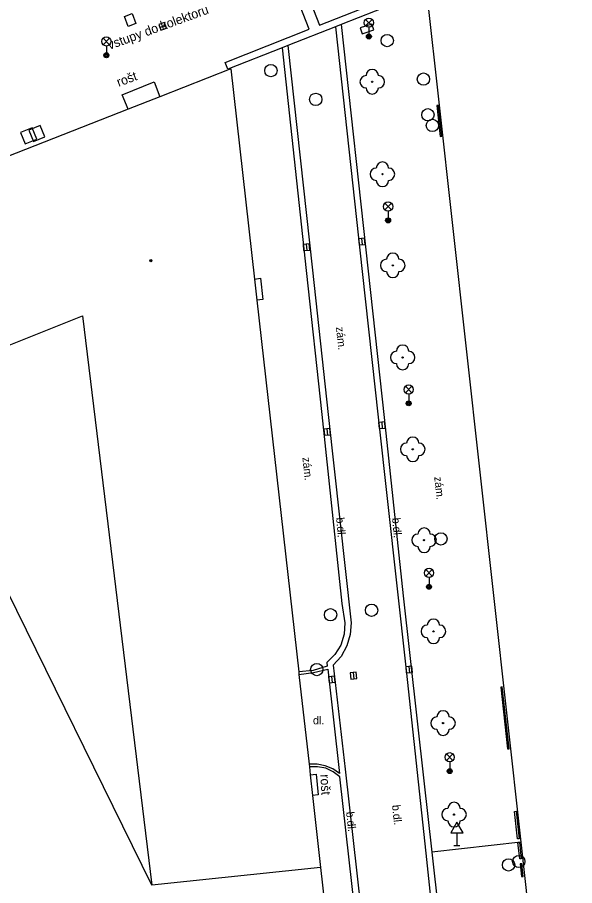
# Model space of a CAD drawing. Extents: x -598341 to -594502, y -1162301 to -1161406.
# Drawn here: x -597857.8 to -597812.6, y -1161565 to -1161494.5 of the extents above; entities that cross this region are included whole.
import ezdxf

# ---------------------------------------------------------------- set-up
doc = ezdxf.new("R2010")
doc.units = 0
for name, color, linetype in [('Vrstva 10', 7, 'Continuous'), ('Vrstva 11', 7, 'Continuous'), ('Vrstva 22', 7, 'Continuous'), ('Vrstva 24', 7, 'Continuous'), ('Vrstva 26', 7, 'Continuous'), ('Vrstva 27', 7, 'Continuous'), ('Vrstva 33', 7, 'Continuous'), ('Vrstva 34', 7, 'Continuous'), ('Vrstva 39', 7, 'Continuous'), ('Vrstva 40', 7, 'Continuous'), ('Vrstva 42', 7, 'Continuous'), ('Vrstva 5', 7, 'Continuous')]:
    doc.layers.add(name, color=color, linetype=linetype)

msp = doc.modelspace()

# ---------------------------------------------------------------- linework, layer by layer
at = {"layer": 'Vrstva 10'}
for points in [[(-597832.03, -1161495.26), (-597835.89, -1161496.78)], [(-597832.03, -1161495.26), (-597829.87, -1161515.13), (-597828.57, -1161526.96), (-597826.29, -1161547.51), (-597824.69, -1161562.35), (-597823.68, -1161571.89), (-597822.03, -1161587.03), (-597820.44, -1161601.59), (-597818.83, -1161616.03), (-597818.07, -1161622.89)], [(-597835.89, -1161496.78), (-597833.9, -1161515.03), (-597832.61, -1161526.75), (-597830.76, -1161543.65), (-597830.82, -1161544.61), (-597831.09, -1161545.53), (-597831.56, -1161546.38), (-597832.2, -1161547.09)], [(-597832.2, -1161547.09), (-597831.25, -1161555.55), (-597828.73, -1161577.99), (-597827.17, -1161591.96), (-597827.31, -1161592.41), (-597827.31, -1161592.92), (-597827.19, -1161593.38), (-597826.94, -1161593.81), (-597825.4, -1161607.71), (-597823.85, -1161621.6), (-597824.07, -1161623.12), (-597824.6, -1161624.55), (-597825.33, -1161625.58), (-597826.2, -1161626.54)]]:
    msp.add_lwpolyline(points, dxfattribs=at)
at = {"layer": 'Vrstva 11'}
for points in [[(-597836.36, -1161496.96), (-597840.77, -1161498.7), (-597840.99, -1161498.15), (-597834.16, -1161495.44), (-597838.87, -1161483.39), (-597838.03, -1161483.06)], [(-597838.03, -1161483.06), (-597833.31, -1161495.12), (-597824.54, -1161491.66), (-597824.34, -1161492.23)], [(-597824.65, -1161492.35), (-597831.55, -1161495.07)], [(-597849.16, -1161494.43), (-597848.54, -1161494.19), (-597848.23, -1161494.99), (-597848.85, -1161495.23), (-597849.16, -1161494.43)], [(-597831.55, -1161495.07), (-597832.03, -1161495.26)], [(-597831.55, -1161495.07), (-597829.38, -1161515.1), (-597828.08, -1161526.98), (-597826.53, -1161541.46), (-597824.84, -1161556.49), (-597824.2, -1161562.28)], [(-597835.89, -1161496.78), (-597836.36, -1161496.96)], [(-597836.36, -1161496.96), (-597834.39, -1161515.05), (-597833.12, -1161526.73), (-597831.5, -1161542.08), (-597831.27, -1161543.67), (-597831.32, -1161544.58), (-597831.59, -1161545.46), (-597832.07, -1161546.24), (-597832.73, -1161546.87), (-597832.7, -1161547.19), (-597833.83, -1161547.53), (-597835.01, -1161547.65)], [(-597848.84, -1161501.95), (-597849.35, -1161500.77), (-597846.75, -1161499.74), (-597846.27, -1161500.94)], [(-597823.67, -1161501.64), (-597823.8, -1161501.65), (-597823.52, -1161504.16), (-597823.39, -1161504.15), (-597823.67, -1161501.64)], [(-597838.59, -1161515.75), (-597838.12, -1161515.68), (-597837.91, -1161517.39), (-597838.4, -1161517.45)], [(-597834.99, -1161547.85), (-597833.8, -1161547.7), (-597832.65, -1161547.41), (-597831.71, -1161555.9), (-597832.25, -1161555.52), (-597832.86, -1161555.26), (-597833.51, -1161555.13), (-597834.17, -1161555.14)], [(-597818.48, -1161548.86), (-597818.61, -1161548.87), (-597818.06, -1161553.89), (-597817.93, -1161553.88), (-597818.48, -1161548.86)], [(-597824.88, -1161624.03), (-597824.49, -1161622.94), (-597824.31, -1161621.67), (-597825.86, -1161607.9), (-597827.41, -1161594.12), (-597827.66, -1161593.64), (-597827.78, -1161593.11), (-597827.78, -1161592.54), (-597827.66, -1161592.04), (-597829.22, -1161578.05), (-597831.67, -1161556.17), (-597832.2, -1161555.75), (-597832.81, -1161555.47), (-597833.47, -1161555.34), (-597834.14, -1161555.36)], [(-597834.07, -1161556), (-597833.6, -1161555.94), (-597833.43, -1161557.64), (-597833.88, -1161557.68)], [(-597817.49, -1161558.97), (-597817.36, -1161558.96), (-597817.11, -1161561.19), (-597817.24, -1161561.2), (-597817.49, -1161558.97)], [(-597816.98, -1161561.47), (-597824.2, -1161562.28)], [(-597817.09, -1161561.49), (-597816.94, -1161562.82), (-597817.07, -1161562.83), (-597817.22, -1161561.5), (-597817.09, -1161561.49)], [(-597824.2, -1161562.28), (-597823.13, -1161571.98), (-597821.53, -1161586.98), (-597819.94, -1161601.53), (-597819.94, -1161601.55)], [(-597816.92, -1161564.26), (-597816.79, -1161564.25), (-597816.9, -1161563.22), (-597817.03, -1161563.23), (-597816.92, -1161564.26)]]:
    msp.add_lwpolyline(points, dxfattribs=at)
at = {"layer": 'Vrstva 22'}
for centre in [(-597829.04, -1161499.72), (-597828.21, -1161507.23), (-597827.37, -1161514.63), (-597826.57, -1161522.11), (-597825.75, -1161529.57), (-597824.83, -1161536.95), (-597824.07, -1161544.35), (-597823.29, -1161551.8), (-597822.4, -1161559.23)]:
    msp.add_circle(centre, 0.05, dxfattribs=at)
for centre, start, end in [((-597829.04, -1161499.22), 0, 180), ((-597829.54, -1161499.72), 90, 270), ((-597828.54, -1161499.72), 270, 90), ((-597829.04, -1161500.22), 180, 0), ((-597828.21, -1161506.73), 0, 180), ((-597828.71, -1161507.23), 90, 270), ((-597827.71, -1161507.23), 270, 90), ((-597828.21, -1161507.73), 180, 0), ((-597827.37, -1161514.13), 0, 180), ((-597827.87, -1161514.63), 90, 270), ((-597826.87, -1161514.63), 270, 90), ((-597827.37, -1161515.13), 180, 0), ((-597826.57, -1161521.61), 0, 180), ((-597827.07, -1161522.11), 90, 270), ((-597826.07, -1161522.11), 270, 90), ((-597826.57, -1161522.61), 180, 0), ((-597826.25, -1161529.57), 90, 270), ((-597825.75, -1161529.07), 0, 180), ((-597825.25, -1161529.57), 270, 90), ((-597825.75, -1161530.07), 180, 0), ((-597824.83, -1161536.45), 0, 180), ((-597825.33, -1161536.95), 90, 270), ((-597824.33, -1161536.95), 270, 90), ((-597824.83, -1161537.45), 180, 0), ((-597824.07, -1161543.85), 0, 180), ((-597824.57, -1161544.35), 90, 270), ((-597823.57, -1161544.35), 270, 90), ((-597824.07, -1161544.85), 180, 0), ((-597823.29, -1161551.3), 0, 180), ((-597823.79, -1161551.8), 90, 270), ((-597822.79, -1161551.8), 270, 90), ((-597823.29, -1161552.3), 180, 0), ((-597822.9, -1161559.23), 90, 270), ((-597822.4, -1161558.73), 0, 180), ((-597821.9, -1161559.23), 270, 90), ((-597822.4, -1161559.73), 180, 0)]:
    msp.add_arc(centre, 0.5, start, end, dxfattribs=at)
at = {"layer": 'Vrstva 24'}
msp.add_lwpolyline([(-597829.867, -1161495.824), (-597828.917, -1161495.511), (-597829.073, -1161495.036), (-597830.023, -1161495.349)], close=True, dxfattribs=at)
at = {"layer": 'Vrstva 26'}
for points in [[(-597857.206, -1161504.771), (-597856.279, -1161504.396), (-597856.654, -1161503.469), (-597857.581, -1161503.844)], [(-597856.536, -1161504.581), (-597855.609, -1161504.206), (-597855.984, -1161503.279), (-597856.911, -1161503.654)]]:
    msp.add_lwpolyline(points, close=True, dxfattribs=at)
at = {"layer": 'Vrstva 27'}
for p, q in [((-597846.285, -1161495.306), (-597845.815, -1161495.134)), ((-597834.403, -1161512.911), (-597834.357, -1161513.409)), ((-597829.903, -1161512.451), (-597829.857, -1161512.949)), ((-597828.273, -1161527.371), (-597828.227, -1161527.869)), ((-597832.723, -1161527.911), (-597832.677, -1161528.409)), ((-597826.073, -1161547.211), (-597826.027, -1161547.709)), ((-597832.343, -1161548.011), (-597832.297, -1161548.509)), ((-597830.583, -1161547.701), (-597830.537, -1161548.199))]:
    msp.add_line(p, q, dxfattribs=at)
for points in [[(-597846.2, -1161495.54), (-597845.729, -1161495.369), (-597845.9, -1161494.9), (-597846.371, -1161495.071)], [(-597834.652, -1161512.934), (-597834.606, -1161513.432), (-597834.108, -1161513.386), (-597834.154, -1161512.888)], [(-597830.152, -1161512.474), (-597830.106, -1161512.972), (-597829.608, -1161512.926), (-597829.654, -1161512.428)], [(-597828.522, -1161527.394), (-597828.476, -1161527.892), (-597827.978, -1161527.846), (-597828.024, -1161527.348)], [(-597832.972, -1161527.934), (-597832.926, -1161528.432), (-597832.428, -1161528.386), (-597832.474, -1161527.888)], [(-597826.322, -1161547.234), (-597826.276, -1161547.732), (-597825.778, -1161547.686), (-597825.824, -1161547.188)], [(-597832.592, -1161548.034), (-597832.546, -1161548.532), (-597832.048, -1161548.486), (-597832.094, -1161547.988)], [(-597830.832, -1161547.724), (-597830.786, -1161548.222), (-597830.288, -1161548.176), (-597830.334, -1161547.678)]]:
    msp.add_lwpolyline(points, close=True, dxfattribs=at)
for centre in [(-597827.82, -1161496.38), (-597837.27, -1161498.82), (-597824.88, -1161499.51), (-597833.63, -1161501.15), (-597824.52, -1161502.4), (-597824.16, -1161503.27), (-597823.46, -1161536.84), (-597832.42, -1161543), (-597829.09, -1161542.64), (-597833.54, -1161547.45), (-597817.97, -1161563.32), (-597817.14, -1161563.04)]:
    msp.add_circle(centre, 0.5, dxfattribs=at)
at = {"layer": 'Vrstva 33'}
for p, q in [((-597829.575, -1161495.19), (-597829.045, -1161494.66)), ((-597829.575, -1161494.66), (-597829.045, -1161495.19)), ((-597829.31, -1161495.3), (-597829.31, -1161496.05)), ((-597850.885, -1161496.71), (-597850.355, -1161496.18)), ((-597850.885, -1161496.18), (-597850.355, -1161496.71)), ((-597850.62, -1161496.82), (-597850.62, -1161497.57)), ((-597828.015, -1161510.12), (-597827.485, -1161509.59)), ((-597828.015, -1161509.59), (-597827.485, -1161510.12)), ((-597827.75, -1161510.23), (-597827.75, -1161510.98)), ((-597826.345, -1161524.98), (-597825.815, -1161524.45)), ((-597826.345, -1161524.45), (-597825.815, -1161524.98)), ((-597826.08, -1161525.09), (-597826.08, -1161525.84)), ((-597824.695, -1161539.87), (-597824.165, -1161539.34)), ((-597824.695, -1161539.34), (-597824.165, -1161539.87)), ((-597824.43, -1161539.98), (-597824.43, -1161540.73)), ((-597823.015, -1161554.84), (-597822.485, -1161554.31)), ((-597823.015, -1161554.31), (-597822.485, -1161554.84)), ((-597822.75, -1161554.95), (-597822.75, -1161555.7))]:
    msp.add_line(p, q, dxfattribs=at)
for centre, radius in [((-597829.31, -1161494.925), 0.375), ((-597850.62, -1161496.445), 0.375), ((-597829.31, -1161496.05), 0.2), ((-597829.31, -1161496.05), 0.145), ((-597829.31, -1161496.05), 0.0876), ((-597850.62, -1161497.57), 0.2), ((-597850.62, -1161497.57), 0.145), ((-597850.62, -1161497.57), 0.0876), ((-597827.75, -1161509.855), 0.375), ((-597827.75, -1161510.98), 0.2), ((-597827.75, -1161510.98), 0.145), ((-597827.75, -1161510.98), 0.0876), ((-597826.08, -1161524.715), 0.375), ((-597826.08, -1161525.84), 0.2), ((-597826.08, -1161525.84), 0.145), ((-597826.08, -1161525.84), 0.0876), ((-597824.43, -1161539.605), 0.375), ((-597824.43, -1161540.73), 0.2), ((-597824.43, -1161540.73), 0.145), ((-597824.43, -1161540.73), 0.0876), ((-597822.75, -1161554.575), 0.375), ((-597822.75, -1161555.7), 0.2), ((-597822.75, -1161555.7), 0.145), ((-597822.75, -1161555.7), 0.0876)]:
    msp.add_circle(centre, radius, dxfattribs=at)
at = {"layer": 'Vrstva 34'}
for p, q in [((-597822.17, -1161560.722), (-597822.17, -1161561.74)), ((-597822.42, -1161561.74), (-597821.92, -1161561.74))]:
    msp.add_line(p, q, dxfattribs=at)
msp.add_lwpolyline([(-597822.67, -1161560.722), (-597821.67, -1161560.722), (-597822.17, -1161559.856)], close=True, dxfattribs=at)
at = {"layer": 'Vrstva 39'}
for radius in [0.09, 0.0398]:
    msp.add_circle((-597847.01, -1161514.25), radius, dxfattribs=at)
at = {"layer": 'Vrstva 5'}
for p, q in [((-597824.65, -1161492.35), (-597823.62, -1161501.38)), ((-597840.51, -1161498.68), (-597846.27, -1161500.94)), ((-597840.51, -1161498.68), (-597838.59, -1161515.75)), ((-597846.27, -1161500.94), (-597848.84, -1161501.95)), ((-597823.62, -1161501.38), (-597816.98, -1161561.47)), ((-597848.84, -1161501.95), (-597872, -1161511.03)), ((-597838.59, -1161515.75), (-597838.4, -1161517.45)), ((-597838.4, -1161517.45), (-597835.01, -1161547.65)), ((-597866.58, -1161524.34), (-597852.57, -1161518.72)), ((-597852.57, -1161518.72), (-597846.94, -1161564.96)), ((-597846.94, -1161564.96), (-597865, -1161528.22)), ((-597835.01, -1161547.65), (-597834.99, -1161547.85)), ((-597834.99, -1161547.85), (-597834.17, -1161555.14)), ((-597834.17, -1161555.14), (-597834.14, -1161555.36)), ((-597834.14, -1161555.36), (-597834.07, -1161556)), ((-597834.07, -1161556), (-597833.88, -1161557.68)), ((-597833.88, -1161557.68), (-597833.23, -1161563.52)), ((-597816.98, -1161561.47), (-597812.61, -1161600.77)), ((-597833.23, -1161563.52), (-597846.94, -1161564.96)), ((-597833.23, -1161563.52), (-597831.06, -1161582.82))]:
    msp.add_line(p, q, dxfattribs=at)

# ---------------------------------------------------------------- texts
at = {"layer": 'Vrstva 40'}
for s, rotation, p in [('zám.', 275.63661, (-597831.98, -1161519.65)), ('zám.', 276.12518, (-597834.71, -1161530.24)), ('zám.', 276.12518, (-597824.01, -1161531.82)), ('b.dl.', 274.70241, (-597831.97, -1161535.12)), ('b.dl.', 274.70241, (-597827.42, -1161535.15)), ('b.dl.', 275.84644, (-597827.43, -1161558.47)), ('b.dl.', 275.84644, (-597831.16, -1161559.02))]:
    msp.add_text(s, height=0.65, rotation=rotation, dxfattribs=at).set_placement(p)
msp.add_text('dl.', height=0.65, dxfattribs=at).set_placement((-597833.85, -1161551.9))
at = {"layer": 'Vrstva 42'}
for s, rotation, p in [('vstupy do kolektoru', 20.13169, (-597850.36, -1161497.13)), ('rošt', 20.52015, (-597849.62, -1161500.14)), ('rošt', 273.10322, (-597833.25, -1161555.98))]:
    msp.add_text(s, height=0.75, rotation=rotation, dxfattribs=at).set_placement(p)

doc.saveas('drawing.dxf')
